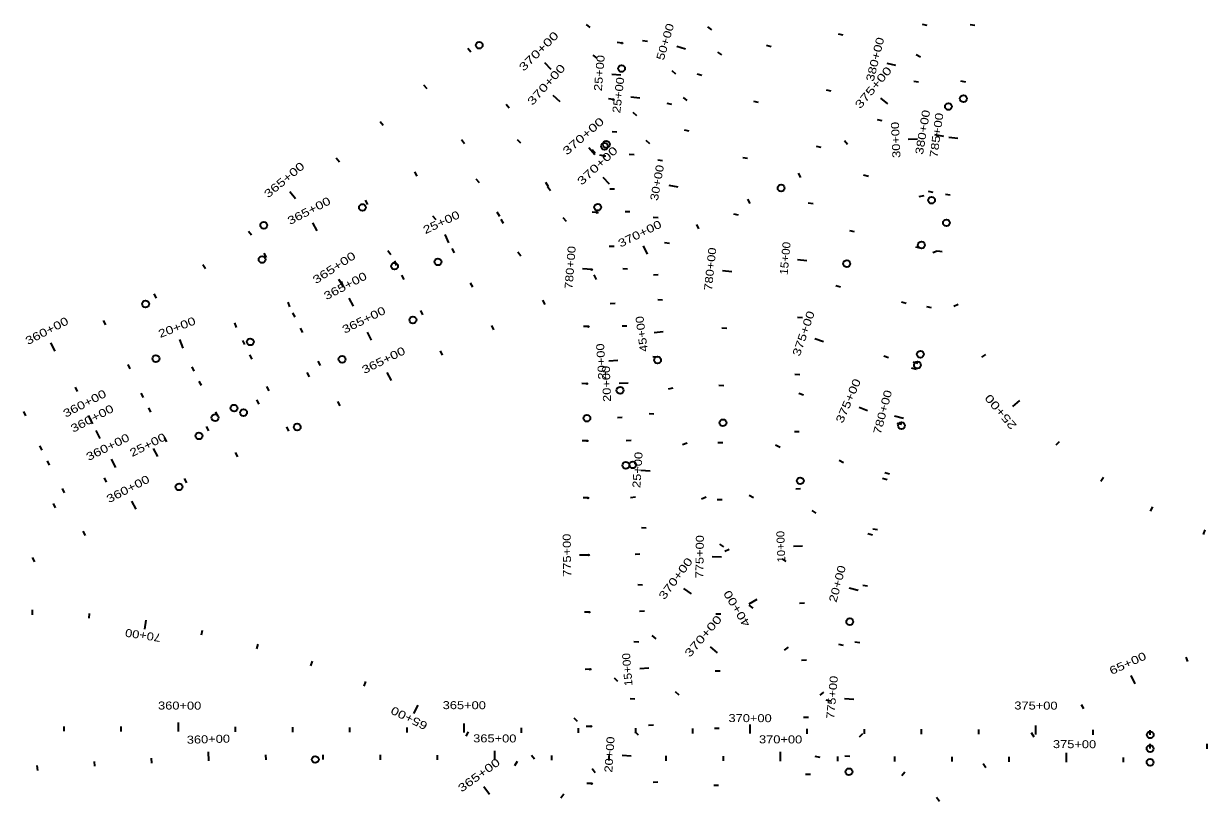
# Model space of a CAD drawing. Extents: x 2357892 to 2370172, y 6966790 to 6985499.
# Drawn here: x 2363276 to 2365347, y 6977898 to 6979260 of the extents above; entities that cross this region are included whole.
import ezdxf
from ezdxf.enums import TextEntityAlignment as Align

# ---------------------------------------------------------------- set-up
doc = ezdxf.new("R2010")
doc.units = 0
doc.header["$LTSCALE"] = 5.6
doc.header["$PDMODE"] = 32
doc.header["$PDSIZE"] = 2.8
doc.layers.add('28', color=7, linetype='Continuous', lineweight=35)
doc.layers.add('7', color=7, linetype='Continuous')

msp = doc.modelspace()

# ---------------------------------------------------------------- linework, layer by layer
at = {"layer": '28'}
for p, q in [((2364267.173, 6979252.703), (2364260.741, 6979258.261)), ((2364479.837, 6979249.066), (2364473.051, 6979254.184)), ((2364856.798, 6979256.241), (2364848.497, 6979258.071)), ((2364940.362, 6979256.206), (2364932, 6979257.728)), ((2364323.101, 6979225.641), (2364314.703, 6979226.952)), ((2364367.346, 6979228.415), (2364358.938, 6979229.667)), ((2364709.954, 6979239.305), (2364701.673, 6979241.219)), ((2364058.696, 6979209.941), (2364053.242, 6979216.461)), ((2364279.289, 6979199.187), (2364272.67, 6979204.519)), ((2364434.26, 6979215.325), (2364418.911, 6979219.842)), ((2364497.312, 6979204.986), (2364490.345, 6979209.856)), ((2364584.109, 6979219.147), (2364575.861, 6979221.2)), ((2364844.906, 6979201.124), (2364837.527, 6979205.344)), ((2364199.044, 6979179.533), (2364187.746, 6979190.863)), ((2364802.087, 6979186.376), (2364786.558, 6979190.231)), ((2364321.055, 6979169.462), (2364305.113, 6979170.817)), ((2364416.89, 6979171.39), (2364410.477, 6979176.969)), ((2364462.69, 6979169.187), (2364454.439, 6979171.23)), ((2363981.993, 6979145.779), (2363976.54, 6979152.299)), ((2364689.066, 6979141.516), (2364680.725, 6979143.152)), ((2364841.713, 6979157.457), (2364833.245, 6979158.188)), ((2364924.172, 6979157.53), (2364915.761, 6979158.76)), ((2364214.544, 6979122.992), (2364202.626, 6979133.668)), ((2364307.68, 6979126.837), (2364299.282, 6979128.148)), ((2364354.128, 6979129.296), (2364338.238, 6979131.168)), ((2364437.205, 6979125.092), (2364430.595, 6979130.436)), ((2364561.655, 6979121.705), (2364553.34, 6979123.469)), ((2364787.958, 6979119.078), (2364775.659, 6979129.312)), ((2364125.679, 6979111.613), (2364120.14, 6979118.06)), ((2364348.678, 6979098.294), (2364342.67, 6979104.306)), ((2364410.033, 6979118.333), (2364401.709, 6979120.05)), ((2363905.291, 6979081.617), (2363899.838, 6979088.137)), ((2364777.992, 6979089.322), (2364769.743, 6979091.37)), ((2364314.067, 6979069.71), (2364305.58, 6979070.178)), ((2364440.357, 6979071.718), (2364432.04, 6979073.471)), ((2364886.146, 6979062.366), (2364870.357, 6979064.956)), ((2364910.572, 6979058.459), (2364894.718, 6979060.611)), ((2364047.484, 6979049.317), (2364042.437, 6979056.157)), ((2364145.899, 6979050.29), (2364139.873, 6979056.285)), ((2364275.533, 6979030.134), (2364265.04, 6979042.213)), ((2364275.903, 6979032.219), (2364270.744, 6979038.974)), ((2364371.671, 6979049.585), (2364365.45, 6979055.377)), ((2364671.448, 6979043.084), (2364663.057, 6979044.442)), ((2364717.628, 6979048.167), (2364712.138, 6979054.655)), ((2364839.651, 6979057.55), (2364823.667, 6979056.833)), ((2363828.589, 6979017.455), (2363823.135, 6979023.975)), ((2364292.334, 6979028.022), (2364283.926, 6979029.271)), ((2364343.943, 6979029.82), (2364335.475, 6979030.556)), ((2364393.922, 6979019.669), (2364385.484, 6979020.69)), ((2364542.616, 6979023.54), (2364534.244, 6979025.012)), ((2363964.886, 6978992.987), (2363960.361, 6979000.182)), ((2364636.053, 6978990.545), (2364631.773, 6978997.889)), ((2364073.543, 6978981.28), (2364067.839, 6978987.582)), ((2364194.359, 6978974.335), (2364189.683, 6978981.434)), ((2364301.029, 6978978.834), (2364290.108, 6978990.527)), ((2364421.439, 6978973.529), (2364405.678, 6978976.281)), ((2364753.898, 6978992.268), (2364745.648, 6978994.316)), ((2363751.887, 6978953.293), (2363741.621, 6978965.565)), ((2364197.812, 6978967.243), (2364192.699, 6978974.033)), ((2364310.042, 6978969.795), (2364301.545, 6978970.011)), ((2364850.648, 6978958.228), (2364842.278, 6978956.742)), ((2364867.386, 6978964.153), (2364859.081, 6978965.966)), ((2364897.122, 6978959.368), (2364888.699, 6978960.511)), ((2363878.341, 6978942.933), (2363874.361, 6978950.444)), ((2364547.028, 6978945.047), (2364543.263, 6978952.668)), ((2364657.12, 6978944.121), (2364648.689, 6978945.198)), ((2363997.675, 6978916.152), (2363992.309, 6978922.744)), ((2364108.974, 6978922.281), (2364104.806, 6978929.689)), ((2364115.892, 6978909.926), (2364111.266, 6978917.056)), ((2364225.625, 6978913.183), (2364220.27, 6978919.785)), ((2364279.383, 6978928.869), (2364270.935, 6978929.806)), ((2364336.801, 6978930.079), (2364328.314, 6978930.557)), ((2364386.037, 6978920.009), (2364377.543, 6978920.328)), ((2364527.014, 6978924.77), (2364518.596, 6978925.949)), ((2363674.974, 6978889.387), (2363669.679, 6978896.036)), ((2363789.63, 6978896.777), (2363782.251, 6978910.974)), ((2364457.374, 6978900.75), (2364453.609, 6978908.371)), ((2364729.803, 6978895.214), (2364721.554, 6978897.262)), ((2364020.167, 6978876.312), (2364013.312, 6978890.77)), ((2364405.96, 6978874.739), (2364397.541, 6978875.908)), ((2363700.9, 6978850.658), (2363696.98, 6978858.2)), ((2363918.502, 6978855.083), (2363913.488, 6978861.947)), ((2364030.175, 6978858.464), (2364026.056, 6978865.899)), ((2364145.824, 6978852.952), (2364140.943, 6978859.911)), ((2364308.983, 6978869.804), (2364300.483, 6978869.768)), ((2364367.72, 6978856.454), (2364360.633, 6978870.798)), ((2364845.39, 6978866.603), (2364837.105, 6978868.504)), ((2364874.514, 6978861.192), (2364866.41, 6978858.626)), ((2364882.991, 6978860.375), (2364874.602, 6978861.744)), ((2363594.132, 6978830.58), (2363589.436, 6978837.666)), ((2363928.368, 6978836.651), (2363925.271, 6978844.567)), ((2364646.098, 6978844.735), (2364630.169, 6978846.233)), ((2363836.241, 6978798.242), (2363827.493, 6978811.638)), ((2363941.776, 6978811.717), (2363937.832, 6978819.246)), ((2364270.038, 6978829.312), (2364254.085, 6978830.539)), ((2364278.067, 6978812.157), (2364274.301, 6978819.778)), ((2364332.708, 6978830.167), (2364324.21, 6978830.385)), ((2364386.431, 6978820.038), (2364377.939, 6978819.653)), ((2364514.868, 6978825.515), (2364498.955, 6978827.181)), ((2363835.151, 6978800.45), (2363832.074, 6978808.373)), ((2364062.016, 6978798.434), (2364057.633, 6978805.716)), ((2364705.171, 6978798.299), (2364696.977, 6978800.561)), ((2363508.472, 6978779.043), (2363504.412, 6978786.511)), ((2363741.932, 6978764.253), (2363738.855, 6978772.176)), ((2363853.196, 6978765.311), (2363845.771, 6978779.484)), ((2364188.413, 6978767.861), (2364184.648, 6978775.481)), ((2364310.892, 6978769.826), (2364302.397, 6978769.538)), ((2364393.938, 6978775.469), (2364385.483, 6978776.344)), ((2364820.112, 6978769.866), (2364811.956, 6978772.26)), ((2363751.119, 6978745.783), (2363746.85, 6978753.134)), ((2363974.61, 6978749.895), (2363970.745, 6978757.465)), ((2364864.311, 6978762.147), (2364856.005, 6978763.953)), ((2364910.842, 6978768.1), (2364903.143, 6978764.499)), ((2363419.835, 6978732.748), (2363415.915, 6978740.29)), ((2363648.713, 6978728.056), (2363645.636, 6978735.979)), ((2364098.759, 6978723.564), (2364094.994, 6978731.185)), ((2364264.046, 6978729.496), (2364255.553, 6978729.863)), ((2364331.668, 6978730.176), (2364323.168, 6978730.135)), ((2364638.395, 6978745.036), (2364629.911, 6978745.55)), ((2363764.615, 6978718.905), (2363760.671, 6978726.434)), ((2363884.992, 6978705.526), (2363877.912, 6978719.874)), ((2364395.102, 6978720.444), (2364379.233, 6978718.397)), ((2364506.194, 6978725.897), (2364497.715, 6978726.486)), ((2364675.629, 6978702.778), (2364660.495, 6978707.97)), ((2363331.105, 6978686.629), (2363323.726, 6978700.826)), ((2363555.494, 6978691.859), (2363549.702, 6978706.774)), ((2363663.381, 6978697.826), (2363659.461, 6978705.369)), ((2364009.105, 6978679.267), (2364005.34, 6978686.888)), ((2363676.035, 6978672.499), (2363672.09, 6978680.028)), ((2363795.315, 6978661.276), (2363791.554, 6978668.898)), ((2364315.766, 6978669.948), (2364299.798, 6978668.931)), ((2364385.387, 6978675.841), (2364376.907, 6978676.42)), ((2364789.09, 6978674.815), (2364781.092, 6978677.693)), ((2364840.585, 6978665.013), (2364832.366, 6978667.18)), ((2364959.01, 6978680.547), (2364951.847, 6978675.971)), ((2363462.423, 6978655.274), (2363459.212, 6978663.145)), ((2363574.648, 6978651.712), (2363570.728, 6978659.254)), ((2363776.368, 6978641.385), (2363772.32, 6978648.859)), ((2363919.451, 6978634.971), (2363912.364, 6978649.315)), ((2364634.019, 6978645.137), (2364625.522, 6978645.367)), ((2364837.828, 6978654.556), (2364829.609, 6978656.723)), ((2363587.455, 6978626.093), (2363583.51, 6978633.622)), ((2363705.638, 6978617.026), (2363701.877, 6978624.648)), ((2364261.412, 6978629.535), (2364252.912, 6978629.616)), ((2364333.682, 6978630.2), (2364317.692, 6978629.634)), ((2364501.002, 6978626.037), (2364492.507, 6978626.33)), ((2363370.507, 6978615.887), (2363367.023, 6978623.64)), ((2363485.915, 6978605.598), (2363481.996, 6978613.14)), ((2364411.99, 6978621.909), (2364403.679, 6978620.127)), ((2364640.311, 6978609.239), (2364632.455, 6978612.483)), ((2363498.874, 6978579.687), (2363494.93, 6978587.216)), ((2363688.433, 6978593.767), (2363684.385, 6978601.242)), ((2363829.797, 6978590.674), (2363826.032, 6978598.295)), ((2364752.435, 6978581.791), (2364737.731, 6978588.1)), ((2365018.194, 6978600.03), (2365005.949, 6978589.731)), ((2363280.021, 6978573.315), (2363276.269, 6978580.942)), ((2363397.183, 6978559.483), (2363389.805, 6978573.681)), ((2363616, 6978572.698), (2363612.197, 6978580.299)), ((2364323.265, 6978570.231), (2364314.791, 6978569.559)), ((2364378.744, 6978576.062), (2364370.263, 6978576.626)), ((2364815.091, 6978568.317), (2364799.62, 6978572.396)), ((2363410.294, 6978533.281), (2363402.869, 6978547.454)), ((2363600.112, 6978546.876), (2363596.245, 6978554.445)), ((2363740.149, 6978546.367), (2363736.373, 6978553.982)), ((2364632.974, 6978545.147), (2364624.475, 6978545.094)), ((2364812.335, 6978557.86), (2364804.116, 6978560.027)), ((2363308.45, 6978513.369), (2363304.531, 6978520.911)), ((2363526.612, 6978527.868), (2363522.801, 6978535.466)), ((2364261.971, 6978529.54), (2364253.472, 6978529.428)), ((2364338.748, 6978530.333), (2364330.267, 6978529.772)), ((2364436.98, 6978525.112), (2364428.845, 6978522.648)), ((2364499.084, 6978526.058), (2364490.585, 6978526.159)), ((2364599.349, 6978518.031), (2364591.705, 6978521.749)), ((2365087.381, 6978527.927), (2365081.646, 6978521.653)), ((2363510.786, 6978501.922), (2363503.603, 6978516.219)), ((2363650.753, 6978501.553), (2363646.91, 6978509.135)), ((2363321.713, 6978486.875), (2363317.769, 6978494.404)), ((2363437.225, 6978483.035), (2363430.052, 6978497.337)), ((2364710.279, 6978491.127), (2364702.683, 6978494.94)), ((2363421.43, 6978457.028), (2363417.614, 6978464.623)), ((2363561.751, 6978455.96), (2363557.843, 6978463.508)), ((2364372.106, 6978476.282), (2364356.141, 6978477.344)), ((2364786.842, 6978461.164), (2364778.623, 6978463.331)), ((2364790.889, 6978471.295), (2364782.608, 6978473.21)), ((2365165.388, 6978465.471), (2365160.521, 6978458.503)), ((2363347.838, 6978438.203), (2363344.027, 6978445.801)), ((2364635.229, 6978445.177), (2364626.734, 6978444.881)), ((2363332.074, 6978412.133), (2363328.258, 6978419.729)), ((2363473.006, 6978409.87), (2363465.631, 6978424.068)), ((2364263.287, 6978429.549), (2364254.788, 6978429.437)), ((2364346.369, 6978430.624), (2364337.895, 6978429.952)), ((2364469.9, 6978430.716), (2364461.997, 6978427.587)), ((2364497.904, 6978426.065), (2364489.405, 6978426.165)), ((2364552.895, 6978429.493), (2364545.492, 6978433.671)), ((2364662.773, 6978403.149), (2364655.418, 6978407.41)), ((2365250.879, 6978413.732), (2365246.963, 6978406.188)), ((2364365.468, 6978376.503), (2364356.986, 6978377.067)), ((2363384.266, 6978363.77), (2363380.348, 6978371.313)), ((2364761.349, 6978364.468), (2364753.13, 6978366.635)), ((2364770.061, 6978373.493), (2364761.718, 6978375.118)), ((2365342.393, 6978373.594), (2365339.495, 6978365.604)), ((2364501.122, 6978343.957), (2364493.988, 6978348.578)), ((2364510.524, 6978339.37), (2364502.907, 6978335.598)), ((2364638.707, 6978345.237), (2364622.716, 6978344.681)), ((2363295.526, 6978317.671), (2363291.607, 6978325.214)), ((2364264.603, 6978329.557), (2364248.604, 6978329.347)), ((2364354.271, 6978330.937), (2364345.798, 6978330.265)), ((2364496.724, 6978326.072), (2364480.725, 6978326.261)), ((2364610.088, 6978318.171), (2364603.001, 6978322.864)), ((2364358.829, 6978276.723), (2364350.348, 6978277.288)), ((2364752.658, 6978275.024), (2364744.264, 6978276.357)), ((2364444.224, 6978261.741), (2364431.352, 6978271.243)), ((2364558.572, 6978251.703), (2364544.872, 6978243.438)), ((2364735.856, 6978267.772), (2364720.385, 6978271.851)), ((2363291.137, 6978233.44), (2363290.895, 6978224.944)), ((2364362.174, 6978231.25), (2364353.7, 6978230.578)), ((2364552.411, 6978236.499), (2364545.617, 6978241.608)), ((2364642.184, 6978245.298), (2364633.689, 6978245.002)), ((2363390.948, 6978227.545), (2363390.188, 6978219.079)), ((2363490.212, 6978215.567), (2363487.811, 6978199.748)), ((2364265.918, 6978229.566), (2364257.419, 6978229.454)), ((2364495.543, 6978226.079), (2364487.044, 6978226.179)), ((2363588.56, 6978197.552), (2363586.774, 6978189.242)), ((2363685.625, 6978173.566), (2363683.335, 6978165.38)), ((2364352.191, 6978176.944), (2364343.71, 6978177.508)), ((2364382.413, 6978183.151), (2364375.896, 6978188.607)), ((2364489.95, 6978158.424), (2364477.761, 6978168.789)), ((2364710.678, 6978170.995), (2364702.427, 6978173.038)), ((2364738.703, 6978176.008), (2364730.267, 6978177.047)), ((2364613.715, 6978168.315), (2364606.825, 6978163.336)), ((2365312.666, 6978143.137), (2365309.582, 6978151.057)), ((2363781.044, 6978143.699), (2363778.259, 6978135.669)), ((2364267.234, 6978129.575), (2364258.735, 6978129.463)), ((2364370.076, 6978131.562), (2364354.126, 6978130.298)), ((2364645.662, 6978145.358), (2364637.167, 6978145.062)), ((2363874.462, 6978108.063), (2363871.192, 6978100.218)), ((2364315.92, 6978108.482), (2364309.748, 6978114.326)), ((2364494.363, 6978126.086), (2364485.864, 6978126.186)), ((2365220.548, 6978104.224), (2365213.906, 6978118.781)), ((2364422.928, 6978084.228), (2364416.794, 6978090.112)), ((2364675.573, 6978089.779), (2364669.119, 6978084.248)), ((2363965.531, 6978066.79), (2363958.484, 6978052.426)), ((2364345.552, 6978077.165), (2364337.071, 6978077.729)), ((2364688.344, 6978073.526), (2364680.027, 6978075.28)), ((2364728.212, 6978076.565), (2364712.273, 6978077.966)), ((2365130.784, 6978060.151), (2365126.823, 6978067.672)), ((2364649.14, 6978045.419), (2364640.645, 6978045.123)), ((2363346.914, 6978021.182), (2363346.942, 6978029.682)), ((2363446.913, 6978020.845), (2363446.942, 6978029.345)), ((2363546.913, 6978020.508), (2363546.967, 6978036.508)), ((2363646.912, 6978020.171), (2363646.941, 6978028.671)), ((2363746.912, 6978019.833), (2363746.94, 6978028.333)), ((2363846.911, 6978019.496), (2363846.94, 6978027.996)), ((2363946.91, 6978019.159), (2363946.939, 6978027.659)), ((2364046.91, 6978018.821), (2364046.964, 6978034.821)), ((2364146.909, 6978018.484), (2364146.938, 6978026.984)), ((2364244.992, 6978038.011), (2364239.188, 6978044.221)), ((2364246.909, 6978018.147), (2364246.937, 6978026.647)), ((2364268.55, 6978029.583), (2364260.051, 6978029.471)), ((2364346.908, 6978017.81), (2364346.937, 6978026.31)), ((2364377.979, 6978031.875), (2364369.505, 6978031.203)), ((2364446.908, 6978017.472), (2364446.936, 6978025.972)), ((2364493.183, 6978026.093), (2364484.683, 6978026.193)), ((2364546.907, 6978017.135), (2364546.961, 6978033.135)), ((2364646.906, 6978016.798), (2364646.935, 6978025.298)), ((2364746.906, 6978016.46), (2364746.935, 6978024.96)), ((2364846.905, 6978016.123), (2364846.934, 6978024.623)), ((2364946.905, 6978015.786), (2364946.933, 6978024.286)), ((2365046.904, 6978015.449), (2365046.958, 6978031.448)), ((2364053.91, 6978020.035), (2364049.707, 6978012.646)), ((2364351.587, 6978014.175), (2364345.815, 6978020.415)), ((2364743.723, 6978016.636), (2364737.749, 6978010.589)), ((2365043.663, 6978011.059), (2365039.282, 6978018.343)), ((2365146.904, 6978015.111), (2365146.932, 6978023.611)), ((2365246.903, 6978014.774), (2365246.932, 6978023.274)), ((2363600.272, 6977969.302), (2363599.806, 6977985.296)), ((2364100.246, 6977970.641), (2364100.3, 6977986.641)), ((2364600.243, 6977968.956), (2364600.297, 6977984.956)), ((2365100.241, 6977967.27), (2365100.294, 6977983.27)), ((2365246.822, 6977990.774), (2365246.851, 6977999.274)), ((2365346.821, 6977990.437), (2365346.85, 6977998.937)), ((2363400.499, 6977959.991), (2363399.955, 6977968.473)), ((2363500.345, 6977965.518), (2363499.949, 6977974.009)), ((2363700.25, 6977971.342), (2363700.15, 6977979.841)), ((2363800.248, 6977971.653), (2363800.277, 6977980.153)), ((2363900.247, 6977971.316), (2363900.276, 6977979.816)), ((2364000.247, 6977970.979), (2364000.275, 6977979.479)), ((2364139.269, 6977967.971), (2364134.624, 6977960.853)), ((2364169.894, 6977972.002), (2364164.48, 6977978.554)), ((2364200.246, 6977970.304), (2364200.274, 6977978.804)), ((2364300.245, 6977969.967), (2364300.274, 6977978.467)), ((2364338.914, 6977977.385), (2364322.949, 6977978.447)), ((2364400.245, 6977969.63), (2364400.273, 6977978.13)), ((2364500.244, 6977969.293), (2364500.273, 6977977.793)), ((2364669.425, 6977975.337), (2364661.051, 6977976.8)), ((2364700.243, 6977968.619), (2364700.271, 6977977.119)), ((2364721.198, 6977976.816), (2364712.709, 6977977.264)), ((2364800.242, 6977968.281), (2364800.271, 6977976.781)), ((2364900.242, 6977967.944), (2364900.27, 6977976.444)), ((2364959.466, 6977957.107), (2364954.679, 6977964.131)), ((2365000.241, 6977967.607), (2365000.27, 6977976.107)), ((2365200.24, 6977966.933), (2365200.269, 6977975.433)), ((2363300.765, 6977952.722), (2363300.073, 6977961.193)), ((2364276.18, 6977948.517), (2364270.793, 6977955.092)), ((2364652.618, 6977945.479), (2364644.123, 6977945.183)), ((2364817.695, 6977949.388), (2364812.243, 6977942.867)), ((2364090.907, 6977910.7), (2364081.488, 6977923.634)), ((2364269.866, 6977929.592), (2364261.367, 6977929.48)), ((2364385.881, 6977932.188), (2364377.408, 6977931.516)), ((2364492.003, 6977926.1), (2364483.503, 6977926.2)), ((2364221.291, 6977910.793), (2364216.22, 6977903.972)), ((2364878.464, 6977898.467), (2364873.286, 6977905.208))]:
    msp.add_line(p, q, dxfattribs=at)
for centre in [(2364073.09, 6979221.983), (2364322.071, 6979181.165), (2364920.069, 6979128.421), (2364893.971, 6979114.589), (2364292.308, 6979044.936), (2364295.47, 6979048.605), (2364601.335, 6978971.879), (2364864.381, 6978950.623), (2363868.869, 6978937.962), (2364280.462, 6978938.461), (2364890.566, 6978911.066), (2363696.347, 6978906.833), (2364846.678, 6978872.259), (2363693.392, 6978846.756), (2363924.996, 6978835.337), (2364000.903, 6978842.693), (2364715.986, 6978839.557), (2363489.583, 6978769), (2363957.16, 6978741.136), (2363672.749, 6978702.695), (2364844.813, 6978681.048), (2363507.699, 6978673.3), (2363833.285, 6978672.206), (2364385.054, 6978670.901), (2364839.818, 6978662.105), (2364319.491, 6978617.83), (2363644.353, 6978586.785), (2363660.831, 6978578.821), (2363610.987, 6978570.186), (2364261.45, 6978569.128), (2364499.498, 6978561.054), (2364811.874, 6978556.113), (2363582.826, 6978538.117), (2363754.737, 6978553.588), (2364329.906, 6978486.454), (2364341.868, 6978487.397), (2364634.731, 6978459.478), (2363548.137, 6978448.9), (2364721.366, 6978212.812), (2365246.903, 6978014.774), (2365246.822, 6977990.774), (2365246.822, 6977990.774), (2363786.433, 6977971.7), (2365246.741, 6977966.776), (2364719.917, 6977950.22)]:
    msp.add_circle(centre, 6, dxfattribs=at)
at = {"layer": '7'}
for p in [(2364323.101, 6979225.641), (2364307.68, 6979126.837), (2364292.334, 6979028.022), (2364279.383, 6978928.869), (2364270.038, 6978829.312), (2364264.046, 6978729.496), (2364261.412, 6978629.535), (2364261.971, 6978529.54), (2364263.287, 6978429.549), (2364264.603, 6978329.557), (2364265.918, 6978229.566), (2364267.234, 6978129.575), (2364268.55, 6978029.583), (2364269.866, 6977929.592)]:
    msp.add_point(p, dxfattribs=at)

# ---------------------------------------------------------------- texts
at = {"layer": '28'}
for s, rotation, width, p in [('50+00', 73.601, 1.25, (2364405.102, 6979226.053)), ('370+00', 44.918, 1.4, (2364182.097, 6979206.413)), ('380+00', 76.058, 1.25, (2364772.419, 6979195.532)), ('25+00', 85.142, 1.2, (2364290.217, 6979172.679)), ('370+00', 48.144, 1.4, (2364195.639, 6979148.347)), ('375+00', 50.236, 1.4, (2364767.855, 6979143.383)), ('25+00', 83.279, 1.2, (2364323.437, 6979133.743)), ('380+00', 80.686, 1.25, (2364855.74, 6979068.517)), ('785+00', 82.27, 1.25, (2364879.982, 6979063.571)), ('370+00', 40.979, 1.4, (2364259.794, 6979057.525)), ('30+00', 92.568, 1.2, (2364808.668, 6979056.476)), ('370+00', 43.044, 1.4, (2364284.648, 6979005.952)), ('365+00', 39.913, 1.35, (2363736.489, 6978980.828)), ('30+00', 80.095, 1.2, (2364391.112, 6978980.066)), ('365+00', 27.464, 1.3, (2363778.562, 6978925.961)), ('25+00', 25.367, 1.3, (2364009.885, 6978905.745)), ('370+00', 26.293, 1.3, (2364357.09, 6978885.779)), ('15+00', 84.627, 1.1, (2364615.296, 6978848.293)), ('365+00', 33.144, 1.35, (2363823.119, 6978826.698)), ('780+00', 85.601, 1.2, (2364239.17, 6978832.226)), ('780+00', 84.024, 1.2, (2364484.114, 6978829.471)), ('365+00', 27.649, 1.3, (2363842.058, 6978794.473)), ('365+00', 26.263, 1.3, (2363874.373, 6978734.854)), ('375+00', 71.065, 1.3, (2364647.086, 6978715.11)), ('360+00', 27.464, 1.3, (2363320.036, 6978715.814)), ('20+00', 21.221, 1.3, (2363546.807, 6978721.741)), ('45+00', 97.351, 1.2, (2364364.241, 6978717.373)), ('365+00', 26.293, 1.3, (2363908.821, 6978664.296)), ('20+00', 93.644, 1.2, (2364293.438, 6978668.837)), ('20+00', 92.029, 1.2, (2364302.693, 6978629.351)), ('375+00', 66.778, 1.3, (2364725.131, 6978596.774)), ('360+00', 27.461, 1.3, (2363386.116, 6978588.668)), ('780+00', 75.23, 1.25, (2364785.586, 6978578.005)), ('25+00', 130.068, 1.4, (2364990.68, 6978584.582)), ('360+00', 27.649, 1.3, (2363399.157, 6978562.443)), ('360+00', 26.636, 1.3, (2363426.465, 6978512.319)), ('25+00', 26.676, 1.3, (2363496.482, 6978516.313)), ('25+00', 86.194, 1.2, (2364357.026, 6978478.115)), ('360+00', 27.451, 1.3, (2363461.942, 6978439.056)), ('775+00', 90.754, 1.2, (2364233.604, 6978329.242)), ('775+00', 89.324, 1.2, (2364465.727, 6978326.521)), ('10+00', 91.993, 1.05, (2364607.717, 6978344.403)), ('370+00', 53.565, 1.35, (2364422.353, 6978284.309)), ('20+00', 75.231, 1.25, (2364706.351, 6978277.46)), ('40+00', 121.101, 1.35, (2364529.847, 6978239.305)), ('370+00', 49.624, 1.4, (2364470.19, 6978183.04)), ('70+00', 171.37, 1.2, (2363486.16, 6978195.953)), ('15+00', 94.533, 1.1, (2364339.129, 6978129.666)), ('65+00', 24.525, 1.3, (2365210.586, 6978133.753)), ('775+00', 84.978, 1.2, (2364697.385, 6978079.891)), ('360+00', 359.807, 1.2, (2363549.095, 6978059.074)), ('365+00', 359.807, 1.2, (2364047.001, 6978059.768)), ('375+00', 359.807, 1.2, (2365046.996, 6978059.098)), ('65+00', 153.87, 1.3, (2363953.639, 6978050.347)), ('370+00', 359.807, 1.2, (2364546.998, 6978037.135)), ('360+00', 1.669, 1.2, (2363599.573, 6978000.295)), ('365+00', 359.807, 1.2, (2364100.375, 6978001.641)), ('20+00', 86.194, 1.2, (2364308.013, 6977979.908)), ('370+00', 359.807, 1.2, (2364600.371, 6977999.956)), ('375+00', 359.807, 1.2, (2365114.563, 6977991.515)), ('365+00', 36.065, 1.35, (2364076.779, 6977938.761))]:
    msp.add_text(s, height=14, rotation=rotation, dxfattribs=dict(at, width=width)).set_placement(p, align=Align.CENTER)

doc.saveas('drawing.dxf')
